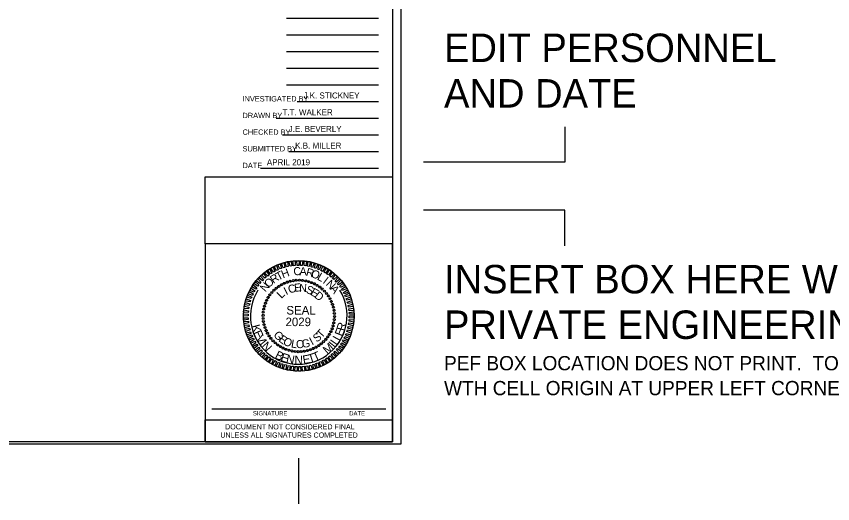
# Model space of a CAD drawing. Extents: x 278618 to 280654, y 171155 to 171855.
# Drawn here: x 280167.8 to 280282.4, y 171515.3 to 171583.8 of the extents above; entities that cross this region are included whole.
import ezdxf

# ---------------------------------------------------------------- set-up
doc = ezdxf.new("R2010")
doc.units = 0
for name, color, linetype in [('Geotech Sheets and Borders Cell', 7, 'Continuous'), ('Scratch_Level_0', 7, 'Continuous'), ('Scratch_Level_4', 7, 'Continuous'), ('Scratch_Level_6', 7, 'Continuous'), ('Sheet Plot Border Inside CELL', 7, 'Continuous'), ('Sheet Professional Seal CELL', 7, 'Continuous'), ('Sheet Sticker Exception Certification CELL', 7, 'Continuous')]:
    doc.layers.add(name, color=color, linetype=linetype)

msp = doc.modelspace()

# ---------------------------------------------------------------- linework, layer by layer
at = {"layer": 'Geotech Sheets and Borders Cell'}
for p, q in [((280205.76, 171583.5), (280218.66, 171583.5)), ((280205.76, 171581.16), (280218.66, 171581.16)), ((280205.76, 171578.82), (280218.66, 171578.82)), ((280205.76, 171576.48), (280218.66, 171576.48)), ((280205.76, 171574.14), (280218.66, 171574.14)), ((280207.27, 171571.8), (280218.66, 171571.8)), ((280204.32, 171569.46), (280218.66, 171569.46)), ((280205.19, 171567.12), (280218.66, 171567.12)), ((280206.1, 171564.78), (280218.66, 171564.78)), ((280202.13, 171562.44), (280218.66, 171562.44)), ((280219.7, 171528.6), (280195.26, 171528.6))]:
    msp.add_line(p, q, dxfattribs=at)
msp.add_lwpolyline([(280070.63, 171628.97), (280220.63, 171628.97), (280220.63, 171523.97), (280070.63, 171523.97)], close=True, dxfattribs=at)
msp.add_lwpolyline([(280220.63, 171551.8), (280220.63, 171551.8), (280194.33, 171551.8), (280194.33, 171523.97), (280220.63, 171523.97), (280220.63, 171551.8)], dxfattribs=at)
at = {"layer": 'Scratch_Level_0'}
msp.add_ellipse((280207.48, 171541.67), major_axis=(4.51, 5.1), ratio=0.993455, start_param=1.731198, end_param=5.992706, dxfattribs=at)
at = {"layer": 'Scratch_Level_4'}
for points in [[(280244.82, 171568.26), (280244.82, 171563.26), (280225.01, 171563.26)], [(280244.82, 171551.51), (280244.82, 171556.51), (280225.01, 171556.51)], [(280207.48, 171515.3), (280207.48, 171521.72)]]:
    msp.add_lwpolyline(points, dxfattribs=at)
at = {"layer": 'Scratch_Level_6'}
msp.add_lwpolyline([(280194.33, 171561.23), (280220.63, 171561.23), (280220.63, 171551.8), (280194.33, 171551.8)], close=True, dxfattribs=at)
msp.add_circle((280207.48, 171541.69), 7.77, dxfattribs=at)
at = {"layer": 'Sheet Plot Border Inside CELL'}
msp.add_lwpolyline([(280055.11, 171523.69), (280221.88, 171523.69), (280221.88, 171629.26), (280055.11, 171629.26)], close=True, dxfattribs=at)
at = {"layer": 'Sheet Professional Seal CELL'}
for p, q in [((280207.13, 171546.68), (280207.13, 171546.68)), ((280207.57, 171546.69), (280207.57, 171546.69)), ((280208.01, 171546.66), (280208.01, 171546.66)), ((280204.32, 171545.58), (280204.32, 171545.58)), ((280204.67, 171545.83), (280204.67, 171545.83)), ((280205.05, 171546.06), (280205.05, 171546.06)), ((280205.44, 171546.26), (280205.44, 171546.26)), ((280205.84, 171546.42), (280205.84, 171546.42)), ((280206.26, 171546.54), (280206.26, 171546.54)), ((280206.7, 171546.62), (280206.7, 171546.62)), ((280208.44, 171546.59), (280208.44, 171546.59)), ((280208.86, 171546.5), (280208.86, 171546.5)), ((280209.28, 171546.36), (280209.28, 171546.36)), ((280209.68, 171546.18), (280209.68, 171546.18)), ((280210.07, 171545.98), (280210.07, 171545.98)), ((280210.43, 171545.73), (280210.43, 171545.73)), ((280203.42, 171544.62), (280203.42, 171544.62)), ((280203.69, 171544.97), (280203.69, 171544.97)), ((280203.99, 171545.28), (280203.99, 171545.28)), ((280210.78, 171545.46), (280210.78, 171545.46)), ((280211.09, 171545.16), (280211.09, 171545.16)), ((280211.39, 171544.83), (280211.39, 171544.83)), ((280211.64, 171544.48), (280211.64, 171544.48)), ((280202.79, 171543.47), (280202.79, 171543.47)), ((280202.97, 171543.87), (280202.97, 171543.87)), ((280203.17, 171544.26), (280203.17, 171544.26)), ((280211.87, 171544.1), (280211.87, 171544.1)), ((280212.07, 171543.71), (280212.07, 171543.71)), ((280212.23, 171543.31), (280212.23, 171543.31)), ((280202.49, 171542.2), (280202.49, 171542.2)), ((280202.56, 171542.63), (280202.56, 171542.63)), ((280202.65, 171543.05), (280202.65, 171543.05)), ((280212.35, 171542.89), (280212.35, 171542.89)), ((280212.43, 171542.45), (280212.43, 171542.45)), ((280202.46, 171541.76), (280202.46, 171541.76)), ((280202.47, 171541.32), (280202.47, 171541.32)), ((280212.47, 171541.14), (280212.47, 171541.14)), ((280212.49, 171542.02), (280212.49, 171542.02)), ((280212.5, 171541.58), (280212.5, 171541.58)), ((280202.53, 171540.89), (280202.53, 171540.89)), ((280202.61, 171540.45), (280202.61, 171540.45)), ((280202.73, 171540.03), (280202.73, 171540.03)), ((280212.17, 171539.87), (280212.17, 171539.87)), ((280212.31, 171540.29), (280212.31, 171540.29)), ((280212.4, 171540.71), (280212.4, 171540.71)), ((280202.89, 171539.63), (280202.89, 171539.63)), ((280203.09, 171539.24), (280203.09, 171539.24)), ((280203.32, 171538.86), (280203.32, 171538.86)), ((280211.54, 171538.72), (280211.54, 171538.72)), ((280211.79, 171539.08), (280211.79, 171539.08)), ((280211.99, 171539.47), (280211.99, 171539.47)), ((280203.57, 171538.51), (280203.57, 171538.51)), ((280203.87, 171538.18), (280203.87, 171538.18)), ((280204.18, 171537.88), (280204.18, 171537.88)), ((280204.53, 171537.61), (280204.53, 171537.61)), ((280210.29, 171537.51), (280210.29, 171537.51)), ((280210.64, 171537.76), (280210.64, 171537.76)), ((280210.97, 171538.06), (280210.97, 171538.06)), ((280211.27, 171538.37), (280211.27, 171538.37)), ((280204.89, 171537.36), (280204.89, 171537.36)), ((280205.28, 171537.16), (280205.28, 171537.16)), ((280205.68, 171536.98), (280205.68, 171536.98)), ((280206.1, 171536.84), (280206.1, 171536.84)), ((280206.52, 171536.75), (280206.52, 171536.75)), ((280206.95, 171536.68), (280206.95, 171536.68)), ((280207.39, 171536.65), (280207.39, 171536.65)), ((280207.83, 171536.66), (280207.83, 171536.66)), ((280208.26, 171536.72), (280208.26, 171536.72)), ((280208.7, 171536.8), (280208.7, 171536.8)), ((280209.12, 171536.92), (280209.12, 171536.92)), ((280209.52, 171537.08), (280209.52, 171537.08)), ((280209.91, 171537.28), (280209.91, 171537.28))]:
    msp.add_line(p, q, dxfattribs=at)
for points in [[(280204.81, 171548.27), (280204.55, 171548.85), (280204.85, 171548.97), (280205.06, 171548.33)], [(280205.3, 171548.43), (280205.07, 171549.03), (280205.38, 171549.12), (280205.51, 171548.5)], [(280205.78, 171548.56), (280205.57, 171549.19), (280205.91, 171549.26), (280205.99, 171548.61)], [(280206.26, 171548.67), (280206.1, 171549.31), (280206.43, 171549.34), (280206.5, 171548.7)], [(280206.74, 171548.73), (280206.63, 171549.37), (280206.97, 171549.41), (280206.98, 171548.76)], [(280207.24, 171548.78), (280207.19, 171549.43), (280207.52, 171549.42), (280207.48, 171548.77)], [(280207.72, 171548.77), (280207.72, 171549.42), (280208.05, 171549.41), (280207.96, 171548.76)], [(280208.22, 171548.74), (280208.26, 171549.39), (280208.59, 171549.33), (280208.46, 171548.7)], [(280208.7, 171548.66), (280208.79, 171549.3), (280209.12, 171549.25), (280208.94, 171548.63)], [(280209.21, 171548.55), (280209.31, 171549.2), (280209.65, 171549.12), (280209.42, 171548.5)], [(280209.69, 171548.42), (280209.84, 171549.04), (280210.15, 171548.94), (280209.9, 171548.35)], [(280203.12, 171547.27), (280202.69, 171547.75), (280202.96, 171547.96), (280203.31, 171547.4)], [(280203.5, 171547.57), (280203.13, 171548.08), (280203.39, 171548.27), (280203.72, 171547.69)], [(280203.94, 171547.82), (280203.57, 171548.36), (280203.88, 171548.52), (280204.13, 171547.94)], [(280204.37, 171548.06), (280204.05, 171548.62), (280204.36, 171548.76), (280204.59, 171548.15)], [(280210.14, 171548.24), (280210.37, 171548.87), (280210.65, 171548.75), (280210.37, 171548.17)], [(280210.59, 171548.05), (280210.84, 171548.64), (280211.15, 171548.5), (280210.81, 171547.94)], [(280211.05, 171547.82), (280211.32, 171548.39), (280211.62, 171548.22), (280211.24, 171547.7)], [(280211.44, 171547.55), (280211.79, 171548.13), (280212.05, 171547.92), (280211.66, 171547.43)], [(280211.85, 171547.25), (280212.22, 171547.8), (280212.48, 171547.58), (280212.04, 171547.11)], [(280202.04, 171546.23), (280201.52, 171546.62), (280201.74, 171546.88), (280202.18, 171546.41)], [(280202.39, 171546.61), (280201.88, 171547.02), (280202.13, 171547.25), (280202.55, 171546.77)], [(280202.72, 171546.96), (280202.28, 171547.4), (280202.52, 171547.64), (280202.91, 171547.1)], [(280212.23, 171546.94), (280212.64, 171547.46), (280212.88, 171547.22), (280212.42, 171546.79)], [(280212.59, 171546.59), (280213.02, 171547.06), (280213.26, 171546.82), (280212.74, 171546.43)], [(280212.94, 171546.23), (280213.4, 171546.68), (280213.61, 171546.41), (280213.08, 171546.03)], [(280201.2, 171545.02), (280200.63, 171545.27), (280200.78, 171545.58), (280201.32, 171545.21)], [(280201.44, 171545.45), (280200.88, 171545.75), (280201.08, 171546.03), (280201.6, 171545.63)], [(280201.74, 171545.85), (280201.2, 171546.19), (280201.39, 171546.48), (280201.87, 171546.04)], [(280213.24, 171545.84), (280213.73, 171546.26), (280213.92, 171545.97), (280213.36, 171545.65)], [(280213.5, 171545.43), (280214.03, 171545.81), (280214.22, 171545.51), (280213.64, 171545.23)], [(280200.8, 171544.12), (280200.18, 171544.3), (280200.31, 171544.61), (280200.91, 171544.33)], [(280201, 171544.56), (280200.38, 171544.79), (280200.53, 171545.1), (280201.1, 171544.78)], [(280213.76, 171544.99), (280214.32, 171545.34), (280214.45, 171545.03), (280213.88, 171544.8)], [(280213.96, 171544.56), (280214.55, 171544.86), (280214.68, 171544.54), (280214.06, 171544.34)], [(280200.52, 171543.16), (280199.9, 171543.24), (280199.97, 171543.58), (280200.6, 171543.37)], [(280200.65, 171543.64), (280200.03, 171543.77), (280200.1, 171544.1), (280200.73, 171543.85)], [(280214.14, 171544.09), (280214.75, 171544.35), (280214.86, 171544.04), (280214.24, 171543.88)], [(280214.3, 171543.61), (280214.94, 171543.84), (280215, 171543.51), (280214.37, 171543.4)], [(280214.42, 171543.13), (280215.05, 171543.32), (280215.11, 171542.98), (280214.48, 171542.92)], [(280200.39, 171542.17), (280199.74, 171542.19), (280199.76, 171542.52), (280200.41, 171542.41)], [(280200.44, 171542.65), (280199.8, 171542.71), (280199.84, 171543.05), (280200.49, 171542.89)], [(280214.51, 171542.65), (280215.16, 171542.79), (280215.19, 171542.45), (280214.55, 171542.41)], [(280214.57, 171542.17), (280215.22, 171542.25), (280215.24, 171541.91), (280214.59, 171541.93)], [(280200.39, 171541.17), (280199.74, 171541.09), (280199.72, 171541.43), (280200.37, 171541.41)], [(280200.38, 171541.67), (280199.73, 171541.64), (280199.73, 171541.98), (280200.38, 171541.91)], [(280200.45, 171540.69), (280199.8, 171540.55), (280199.77, 171540.89), (280200.41, 171540.93)], [(280214.57, 171541.17), (280215.22, 171541.15), (280215.2, 171540.82), (280214.55, 171540.93)], [(280214.58, 171541.67), (280215.23, 171541.7), (280215.23, 171541.36), (280214.58, 171541.43)], [(280200.54, 171540.21), (280199.91, 171540.02), (280199.85, 171540.36), (280200.48, 171540.42)], [(280200.66, 171539.73), (280200.02, 171539.5), (280199.96, 171539.83), (280200.59, 171539.94)], [(280214.44, 171540.18), (280215.06, 171540.1), (280214.99, 171539.76), (280214.36, 171539.97)], [(280214.52, 171540.69), (280215.16, 171540.63), (280215.12, 171540.29), (280214.47, 171540.45)], [(280200.82, 171539.25), (280200.21, 171538.99), (280200.1, 171539.3), (280200.72, 171539.46)], [(280201, 171538.78), (280200.41, 171538.48), (280200.28, 171538.8), (280200.9, 171539)], [(280213.96, 171538.78), (280214.58, 171538.55), (280214.43, 171538.24), (280213.86, 171538.56)], [(280214.16, 171539.22), (280214.78, 171539.04), (280214.65, 171538.73), (280214.05, 171539.01)], [(280214.31, 171539.7), (280214.93, 171539.57), (280214.86, 171539.24), (280214.23, 171539.49)], [(280201.2, 171538.35), (280200.64, 171538), (280200.51, 171538.31), (280201.08, 171538.54)], [(280201.46, 171537.91), (280200.93, 171537.53), (280200.74, 171537.83), (280201.32, 171538.11)], [(280201.72, 171537.5), (280201.23, 171537.08), (280201.04, 171537.37), (280201.6, 171537.69)], [(280213.22, 171537.49), (280213.76, 171537.15), (280213.57, 171536.86), (280213.09, 171537.3)], [(280213.52, 171537.89), (280214.08, 171537.59), (280213.88, 171537.31), (280213.36, 171537.71)], [(280213.76, 171538.32), (280214.33, 171538.07), (280214.18, 171537.76), (280213.64, 171538.13)], [(280202.02, 171537.11), (280201.56, 171536.66), (280201.35, 171536.93), (280201.88, 171537.31)], [(280202.37, 171536.75), (280201.94, 171536.28), (280201.7, 171536.52), (280202.22, 171536.91)], [(280202.73, 171536.4), (280202.32, 171535.88), (280202.08, 171536.12), (280202.54, 171536.55)], [(280212.24, 171536.38), (280212.68, 171535.94), (280212.44, 171535.7), (280212.05, 171536.24)], [(280212.57, 171536.73), (280213.08, 171536.32), (280212.83, 171536.09), (280212.41, 171536.57)], [(280212.92, 171537.11), (280213.44, 171536.72), (280213.22, 171536.46), (280212.78, 171536.93)], [(280203.11, 171536.09), (280202.74, 171535.54), (280202.48, 171535.76), (280202.92, 171536.23)], [(280203.52, 171535.79), (280203.17, 171535.21), (280202.91, 171535.42), (280203.3, 171535.91)], [(280203.91, 171535.52), (280203.64, 171534.95), (280203.34, 171535.12), (280203.72, 171535.64)], [(280204.37, 171535.29), (280204.12, 171534.7), (280203.81, 171534.84), (280204.15, 171535.4)], [(280210.59, 171535.28), (280210.91, 171534.72), (280210.6, 171534.58), (280210.37, 171535.19)], [(280211.02, 171535.52), (280211.39, 171534.98), (280211.08, 171534.82), (280210.83, 171535.4)], [(280211.46, 171535.77), (280211.83, 171535.26), (280211.57, 171535.07), (280211.24, 171535.65)], [(280211.84, 171536.07), (280212.27, 171535.59), (280212, 171535.38), (280211.65, 171535.94)], [(280204.82, 171535.1), (280204.59, 171534.47), (280204.31, 171534.59), (280204.59, 171535.17)], [(280205.27, 171534.92), (280205.12, 171534.3), (280204.81, 171534.4), (280205.06, 171534.99)], [(280205.75, 171534.79), (280205.65, 171534.14), (280205.31, 171534.22), (280205.54, 171534.84)], [(280206.26, 171534.68), (280206.17, 171534.04), (280205.84, 171534.09), (280206.02, 171534.71)], [(280206.74, 171534.6), (280206.7, 171533.95), (280206.37, 171534.01), (280206.5, 171534.64)], [(280207.24, 171534.57), (280207.24, 171533.92), (280206.91, 171533.93), (280207, 171534.58)], [(280207.72, 171534.56), (280207.77, 171533.91), (280207.44, 171533.92), (280207.48, 171534.57)], [(280208.22, 171534.61), (280208.33, 171533.97), (280207.99, 171533.93), (280207.98, 171534.58)], [(280208.7, 171534.67), (280208.86, 171534.03), (280208.53, 171534), (280208.46, 171534.64)], [(280209.18, 171534.78), (280209.39, 171534.15), (280209.05, 171534.08), (280208.97, 171534.73)], [(280209.66, 171534.91), (280209.89, 171534.31), (280209.58, 171534.22), (280209.45, 171534.84)], [(280210.15, 171535.07), (280210.41, 171534.49), (280210.11, 171534.37), (280209.9, 171535.01)]]:
    msp.add_lwpolyline(points, close=True, dxfattribs=at)
for centre, major_axis in [((280206.27, 171546.54), (-0.035, 0.14)), ((280206.7, 171546.63), (-0.023, 0.142)), ((280207.13, 171546.68), (-0.01, 0.144)), ((280207.57, 171546.69), (0.003, 0.144)), ((280208.01, 171546.66), (0.015, 0.143)), ((280208.44, 171546.6), (0.027, 0.141)), ((280208.86, 171546.49), (0.04, 0.138)), ((280204.32, 171545.57), (-0.091, 0.112)), ((280204.68, 171545.83), (-0.081, 0.119)), ((280205.05, 171546.06), (-0.07, 0.126)), ((280205.44, 171546.25), (-0.059, 0.132)), ((280205.85, 171546.41), (-0.047, 0.136)), ((280209.28, 171546.35), (0.052, 0.134)), ((280209.68, 171546.18), (0.063, 0.129)), ((280210.06, 171545.97), (0.074, 0.123)), ((280210.43, 171545.73), (0.085, 0.116)), ((280210.77, 171545.46), (0.094, 0.109)), ((280203.18, 171544.26), (-0.123, 0.074)), ((280203.42, 171544.62), (-0.116, 0.085)), ((280203.7, 171544.96), (-0.109, 0.094)), ((280204, 171545.28), (-0.1, 0.104)), ((280211.09, 171545.16), (0.104, 0.1)), ((280211.38, 171544.83), (0.112, 0.091)), ((280211.64, 171544.48), (0.119, 0.081)), ((280202.66, 171543.05), (-0.138, 0.04)), ((280202.8, 171543.47), (-0.134, 0.052)), ((280202.97, 171543.87), (-0.129, 0.063)), ((280211.87, 171544.1), (0.126, 0.07)), ((280212.06, 171543.71), (0.132, 0.059)), ((280212.22, 171543.3), (0.136, 0.047)), ((280202.49, 171542.2), (-0.143, 0.015)), ((280202.56, 171542.63), (-0.141, 0.027)), ((280212.35, 171542.89), (0.14, 0.035)), ((280212.44, 171542.46), (0.142, 0.023)), ((280212.48, 171542.02), (0.144, 0.01)), ((280202.47, 171541.76), (-0.144, 0.003)), ((280202.48, 171541.32), (-0.144, -0.01)), ((280202.53, 171540.89), (-0.142, -0.023)), ((280212.47, 171541.15), (0.143, -0.015)), ((280212.5, 171541.58), (0.144, -0.003)), ((280202.61, 171540.46), (-0.14, -0.035)), ((280202.74, 171540.04), (-0.136, -0.047)), ((280202.9, 171539.63), (-0.132, -0.059)), ((280212.16, 171539.87), (0.134, -0.052)), ((280212.3, 171540.29), (0.138, -0.04)), ((280212.4, 171540.71), (0.141, -0.027)), ((280203.09, 171539.24), (-0.126, -0.07)), ((280203.32, 171538.87), (-0.119, -0.081)), ((280203.58, 171538.52), (-0.112, -0.091)), ((280211.54, 171538.72), (0.116, -0.085)), ((280211.78, 171539.09), (0.123, -0.074)), ((280211.99, 171539.47), (0.129, -0.063)), ((280203.87, 171538.19), (-0.104, -0.1)), ((280204.19, 171537.89), (-0.094, -0.109)), ((280204.53, 171537.61), (-0.085, -0.116)), ((280204.9, 171537.37), (-0.074, -0.123)), ((280210.29, 171537.51), (0.081, -0.119)), ((280210.64, 171537.77), (0.091, -0.112)), ((280210.97, 171538.06), (0.1, -0.104)), ((280211.27, 171538.38), (0.109, -0.094)), ((280205.28, 171537.16), (-0.063, -0.129)), ((280205.68, 171536.99), (-0.052, -0.134)), ((280206.1, 171536.85), (-0.04, -0.138)), ((280206.52, 171536.75), (-0.027, -0.141)), ((280206.96, 171536.68), (-0.015, -0.143)), ((280207.39, 171536.66), (-0.003, -0.144)), ((280207.83, 171536.67), (0.01, -0.144)), ((280208.27, 171536.72), (0.023, -0.142)), ((280208.69, 171536.8), (0.035, -0.14)), ((280209.11, 171536.93), (0.047, -0.136)), ((280209.52, 171537.09), (0.059, -0.132)), ((280209.91, 171537.28), (0.07, -0.126))]:
    msp.add_ellipse(centre, major_axis=major_axis, ratio=0.999708, dxfattribs=at)
at = {"layer": 'Sheet Sticker Exception Certification CELL'}
for p, q in [((280194.33, 171523.97), (280194.33, 171527.06)), ((280194.33, 171527.06), (280220.63, 171527.06)), ((280220.63, 171527.06), (280220.63, 171523.97)), ((280194.33, 171523.97), (280220.63, 171523.97))]:
    msp.add_line(p, q, dxfattribs=at)

# ---------------------------------------------------------------- texts
at = {"layer": 'Geotech Sheets and Borders Cell'}
for s, height, p in [('J.K. STICKNEY', 0.84, (280208.15, 171572.22)), ('INVESTIGATED BY', 0.7488, (280199.59, 171571.8)), ('DRAWN BY', 0.749, (280199.59, 171569.46)), ('T.T. WALKER', 0.84, (280205.2, 171569.87)), ('CHECKED BY', 0.749, (280199.59, 171567.12)), ('J.E. BEVERLY', 0.84, (280206.07, 171567.53)), ('SUBMITTED BY', 0.7488, (280199.59, 171564.78)), ('K.B. MILLER', 0.84, (280206.98, 171565.19)), ('DATE', 0.749, (280199.59, 171562.44)), ('APRIL 2019', 0.84, (280203.01, 171562.84)), ('SIGNATURE', 0.6, (280201.05, 171527.7)), ('DATE', 0.6, (280214.57, 171527.7))]:
    msp.add_text(s, height=height, dxfattribs=at).set_placement(p)
at = {"layer": 'Scratch_Level_4'}
for s, height, p in [('EDIT PERSONNEL', 4, (280227.88, 171577.34)), ('AND DATE', 4, (280227.88, 171570.94)), ('INSERT BOX HERE WITH SIZE AS SHOWN FOR', 4, (280227.88, 171544.84)), ('PRIVATE ENGINEERING FIRM (if applicable)', 4, (280227.88, 171538.44)), ('PEF BOX LOCATION DOES NOT PRINT.  TO ADD PEF BOX, PLACE CELL "TitleSht_PEFBox_Insert"', 2, (280227.88, 171534.04)), ('WTH CELL ORIGIN AT UPPER LEFT CORNER OF BOX AND ADD PEF LOGO/NAME/OFFICE LOCATION.', 2, (280227.88, 171530.54))]:
    msp.add_text(s, height=height, dxfattribs=at).set_placement(p)
at = {"layer": 'Sheet Professional Seal CELL'}
for s, height, rotation, p in [('T', 1.13, 27.8198, (280204.62, 171546.61)), ('H', 1.13, 20.6195, (280205.27, 171546.94)), ('C', 1.13, 6.2199, (280206.79, 171547.34)), ('A', 1.13, 359.0203, (280207.58, 171547.4)), ('R', 1.13, 344.6211, (280208.42, 171547.36)), ('O', 1.13, 337.4212, (280209.09, 171547.21)), ('O', 1.13, 42.2217, (280203.25, 171545.55)), ('R', 1.13, 35.0205, (280203.94, 171546.17)), ('L', 1.13, 330.2209, (280209.97, 171546.84)), ('I', 1.13, 323.0201, (280210.78, 171546.36)), ('N', 1.13, 315.8189, (280211.21, 171546.05)), ('N', 1.13, 49.4235, (280202.79, 171544.97)), ('I', 1.13, 25.967, (280205.71, 171544.59)), ('C', 1.13, 16.6111, (280206.16, 171544.81)), ('E', 1.13, 7.2556, (280206.91, 171545.04)), ('N', 1.13, 357.9004, (280207.52, 171545.06)), ('S', 1.13, 339.1896, (280208.39, 171544.96)), ('E', 1.13, 329.8335, (280209.02, 171544.7)), ('A', 1.13, 308.6172, (280211.8, 171545.46)), ('L', 1.13, 44.6812, (280205.04, 171544.05)), ('D', 1.13, 320.4766, (280209.58, 171544.36)), ('K', 1.2, 285.498, (280200.81, 171540.29)), ('T', 1.13, 48.3432, (280210.69, 171538.48)), ('E', 1.2, 67.992, (280213.59, 171538.71)), ('R', 1.2, 75.0033, (280213.91, 171539.48)), ('E', 1.2, 293.7671, (280201.07, 171539.35)), ('V', 1.2, 300.878, (280201.4, 171538.58)), ('G', 1.13, 312.9799, (280203.85, 171538.94)), ('E', 1.13, 322.3369, (280204.56, 171538.2)), ('I', 1.13, 27.8271, (280209.33, 171537.54)), ('S', 1.13, 37.1844, (280210, 171537.91)), ('L', 1.2, 61.8126, (280213.23, 171538.06)), ('I', 1.2, 309.145, (280201.9, 171537.74)), ('N', 1.2, 312.9563, (280202.17, 171537.38)), ('O', 1.13, 331.6932, (280205.17, 171537.76)), ('L', 1.13, 350.4042, (280206.34, 171537.27)), ('O', 1.13, 359.7594, (280207.09, 171537.16)), ('G', 1.13, 9.1148, (280208, 171537.17)), ('M', 1.2, 40.5628, (280211.5, 171536.21)), ('I', 1.2, 51.9002, (280212.51, 171537.12)), ('L', 1.2, 55.639, (280212.8, 171537.46)), ('B', 1.2, 333.9336, (280204.03, 171535.78)), ('E', 1.2, 341.6352, (280204.84, 171535.38)), ('T', 1.2, 17.1032, (280208.97, 171535.04)), ('T', 1.2, 23.8189, (280209.74, 171535.26)), ('N', 1.2, 348.7363, (280205.64, 171535.11)), ('N', 1.2, 359.4209, (280206.88, 171534.89)), ('E', 1.2, 10.0674, (280208.14, 171534.9))]:
    msp.add_text(s, height=height, rotation=rotation, dxfattribs=at).set_placement(p)
for s, p in [('SEAL', (280205.75, 171541.87)), ('2029', (280205.63, 171540.24))]:
    msp.add_text(s, height=1.2, dxfattribs=at).set_placement(p)
at = {"layer": 'Sheet Sticker Exception Certification CELL'}
for s, p in [('DOCUMENT NOT CONSIDERED FINAL', (280197.14, 171525.74)), ('UNLESS ALL SIGNATURES COMPLETED', (280196.47, 171524.58))]:
    msp.add_text(s, height=0.723, dxfattribs=at).set_placement(p)

doc.saveas('drawing.dxf')
